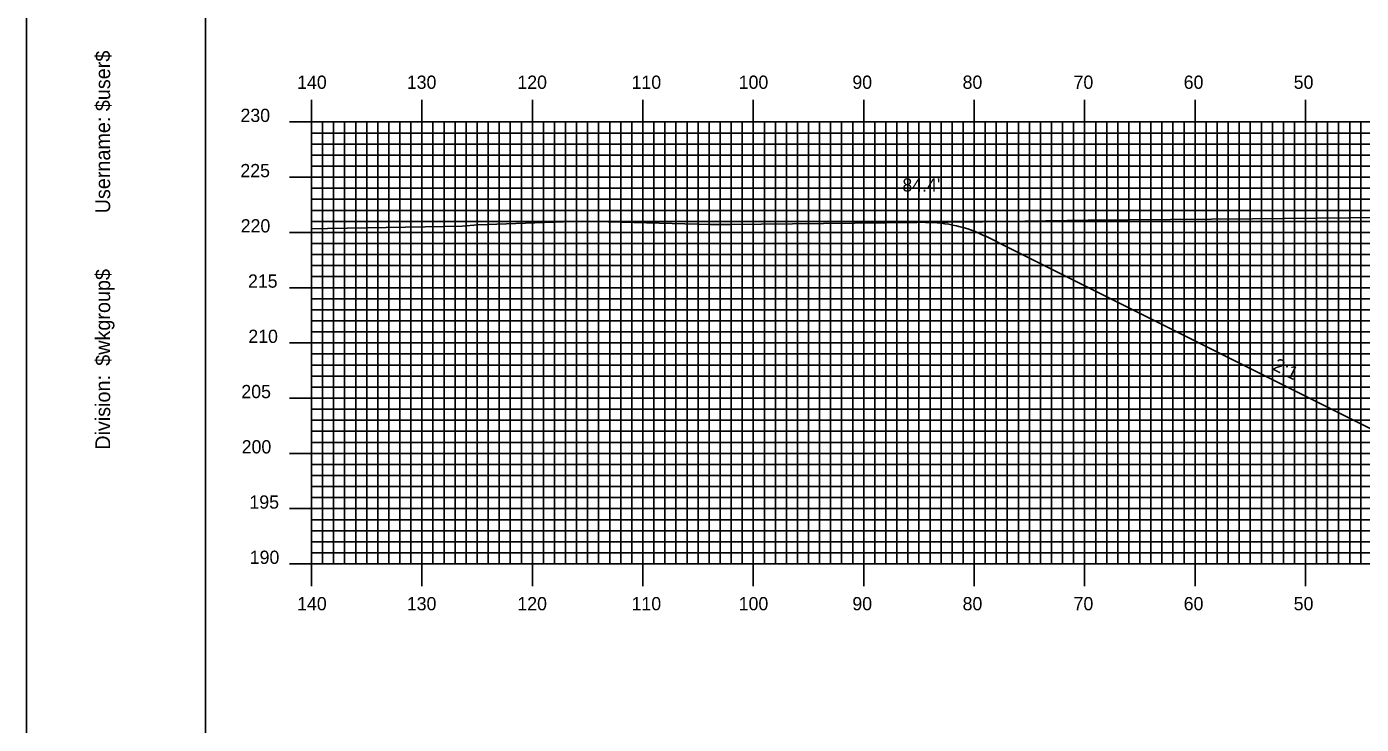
# Model space of a CAD drawing. Extents: x 1800749 to 1801092, y 442591 to 442811.
# Drawn here: x 1800748.8 to 1800869.6, y 442654.2 to 442717.3 of the extents above; entities that cross this region are included whole.
import ezdxf

# ---------------------------------------------------------------- set-up
doc = ezdxf.new("R2010")
doc.units = 0
for name, color, linetype in [('ANNOTATION', 7, 'Continuous'), ('BORDER', 7, 'Continuous'), ('D_Roadway_SlopeLines', 7, 'Continuous'), ('D_Text_Standard', 7, 'Continuous'), ('H_V ANNOTATION', 7, 'Continuous'), ('MAJOR', 7, 'Continuous'), ('MINOR', 7, 'Continuous'), ('PLOT BOUNDARY', 7, 'Continuous'), ('S_Roadway_Centerline', 7, 'Continuous')]:
    doc.layers.add(name, color=color, linetype=linetype)

msp = doc.modelspace()

# ---------------------------------------------------------------- linework, layer by layer
at = {"layer": 'ANNOTATION'}
msp.add_line((1800774.55, 442688.67), (1800774.55, 442689.27), dxfattribs=at)
msp.add_arc((1800830.24, 442687.58), 12, 63.4349, 90.4821, dxfattribs=at)
msp.add_arc((1800830.24, 442687.58), 12, 63.4349, 90.4821, dxfattribs=at)
at = {"layer": 'BORDER'}
msp.add_lwpolyline([(1800764.95, 442596.67), (1801084.95, 442596.67), (1801084.95, 442806.67), (1800764.95, 442806.67)], close=True, dxfattribs=at)
at = {"layer": 'D_Roadway_SlopeLines'}
for p in [(1800835.6, 442698.32), (1800880.38, 442675.93)]:
    msp.add_line(p, (1800837.81, 442697.21), dxfattribs=at)
at = {"layer": 'MAJOR'}
for p, q in [((1800774.55, 442710.67), (1800774.55, 442708.67)), ((1800784.55, 442710.67), (1800784.55, 442708.67)), ((1800794.55, 442710.67), (1800794.55, 442708.67)), ((1800804.55, 442710.67), (1800804.55, 442708.67)), ((1800814.55, 442710.67), (1800814.55, 442708.67)), ((1800824.55, 442710.67), (1800824.55, 442708.67)), ((1800834.55, 442710.67), (1800834.55, 442708.67)), ((1800844.55, 442710.67), (1800844.55, 442708.67)), ((1800854.55, 442710.67), (1800854.55, 442708.67)), ((1800864.55, 442710.67), (1800864.55, 442708.67)), ((1800772.55, 442708.67), (1800774.55, 442708.67)), ((1800774.55, 442708.67), (1801054.55, 442708.67)), ((1800774.55, 442668.67), (1800774.55, 442708.67)), ((1800774.55, 442668.67), (1800774.55, 442708.67)), ((1800774.55, 442708.67), (1801054.55, 442708.67)), ((1800784.55, 442668.67), (1800784.55, 442708.67)), ((1800794.55, 442668.67), (1800794.55, 442708.67)), ((1800804.55, 442668.67), (1800804.55, 442708.67)), ((1800814.55, 442668.67), (1800814.55, 442708.67)), ((1800824.55, 442668.67), (1800824.55, 442708.67)), ((1800834.55, 442668.67), (1800834.55, 442708.67)), ((1800844.55, 442668.67), (1800844.55, 442708.67)), ((1800854.55, 442668.67), (1800854.55, 442708.67)), ((1800864.55, 442668.67), (1800864.55, 442708.67)), ((1800772.55, 442703.67), (1800774.55, 442703.67)), ((1800774.55, 442703.67), (1801054.55, 442703.67)), ((1800772.55, 442698.67), (1800774.55, 442698.67)), ((1800774.55, 442698.67), (1801054.55, 442698.67)), ((1800772.55, 442693.67), (1800774.55, 442693.67)), ((1800774.55, 442693.67), (1801054.55, 442693.67)), ((1800772.55, 442688.67), (1800774.55, 442688.67)), ((1800774.55, 442688.67), (1801054.55, 442688.67)), ((1800772.55, 442683.67), (1800774.55, 442683.67)), ((1800774.55, 442683.67), (1801054.55, 442683.67)), ((1800772.55, 442678.67), (1800774.55, 442678.67)), ((1800774.55, 442678.67), (1801054.55, 442678.67)), ((1800772.55, 442673.67), (1800774.55, 442673.67)), ((1800774.55, 442673.67), (1801054.55, 442673.67)), ((1800772.55, 442668.67), (1800774.55, 442668.67)), ((1800774.55, 442668.67), (1801054.55, 442668.67)), ((1800774.55, 442668.67), (1801054.55, 442668.67)), ((1800774.55, 442666.66), (1800774.55, 442668.67)), ((1800784.55, 442666.66), (1800784.55, 442668.67)), ((1800794.55, 442666.66), (1800794.55, 442668.67)), ((1800804.55, 442666.66), (1800804.55, 442668.67)), ((1800814.55, 442666.66), (1800814.55, 442668.67)), ((1800824.55, 442666.66), (1800824.55, 442668.67)), ((1800834.55, 442666.66), (1800834.55, 442668.67)), ((1800844.55, 442666.66), (1800844.55, 442668.67)), ((1800854.55, 442666.66), (1800854.55, 442668.67)), ((1800864.55, 442666.66), (1800864.55, 442668.67))]:
    msp.add_line(p, q, dxfattribs=at)
at = {"layer": 'MINOR'}
for p, q in [((1800774.55, 442707.67), (1801054.55, 442707.67)), ((1800774.55, 442707.67), (1800776.55, 442707.67)), ((1800775.55, 442668.67), (1800775.55, 442708.67)), ((1800776.55, 442668.67), (1800776.55, 442708.67)), ((1800777.55, 442668.67), (1800777.55, 442708.67)), ((1800778.55, 442668.67), (1800778.55, 442708.67)), ((1800779.55, 442668.67), (1800779.55, 442708.67)), ((1800780.55, 442668.67), (1800780.55, 442708.67)), ((1800781.55, 442668.67), (1800781.55, 442708.67)), ((1800782.55, 442668.67), (1800782.55, 442708.67)), ((1800783.55, 442668.67), (1800783.55, 442708.67)), ((1800785.55, 442668.67), (1800785.55, 442708.67)), ((1800786.55, 442668.67), (1800786.55, 442708.67)), ((1800787.55, 442668.67), (1800787.55, 442708.67)), ((1800788.55, 442668.67), (1800788.55, 442708.67)), ((1800789.55, 442668.67), (1800789.55, 442708.67)), ((1800790.55, 442668.67), (1800790.55, 442708.67)), ((1800791.55, 442668.67), (1800791.55, 442708.67)), ((1800792.55, 442668.67), (1800792.55, 442708.67)), ((1800793.55, 442668.67), (1800793.55, 442708.67)), ((1800795.55, 442668.67), (1800795.55, 442708.67)), ((1800796.55, 442668.67), (1800796.55, 442708.67)), ((1800797.55, 442668.67), (1800797.55, 442708.67)), ((1800798.55, 442668.67), (1800798.55, 442708.67)), ((1800799.55, 442668.67), (1800799.55, 442708.67)), ((1800800.55, 442668.67), (1800800.55, 442708.67)), ((1800801.55, 442668.67), (1800801.55, 442708.67)), ((1800802.55, 442668.67), (1800802.55, 442708.67)), ((1800803.55, 442668.67), (1800803.55, 442708.67)), ((1800805.55, 442668.67), (1800805.55, 442708.67)), ((1800806.55, 442668.67), (1800806.55, 442708.67)), ((1800807.55, 442668.67), (1800807.55, 442708.67)), ((1800808.55, 442668.67), (1800808.55, 442708.67)), ((1800809.55, 442668.67), (1800809.55, 442708.67)), ((1800810.55, 442668.67), (1800810.55, 442708.67)), ((1800811.55, 442668.67), (1800811.55, 442708.67)), ((1800812.55, 442668.67), (1800812.55, 442708.67)), ((1800813.55, 442668.67), (1800813.55, 442708.67)), ((1800815.55, 442668.67), (1800815.55, 442708.67)), ((1800816.55, 442668.67), (1800816.55, 442708.67)), ((1800817.55, 442668.67), (1800817.55, 442708.67)), ((1800818.55, 442668.67), (1800818.55, 442708.67)), ((1800819.55, 442668.67), (1800819.55, 442708.67)), ((1800820.55, 442668.67), (1800820.55, 442708.67)), ((1800821.55, 442668.67), (1800821.55, 442708.67)), ((1800822.55, 442668.67), (1800822.55, 442708.67)), ((1800823.55, 442668.67), (1800823.55, 442708.67)), ((1800825.55, 442668.67), (1800825.55, 442708.67)), ((1800826.55, 442668.67), (1800826.55, 442708.67)), ((1800827.55, 442668.67), (1800827.55, 442708.67)), ((1800828.55, 442668.67), (1800828.55, 442708.67)), ((1800829.55, 442668.67), (1800829.55, 442708.67)), ((1800830.55, 442668.67), (1800830.55, 442708.67)), ((1800831.55, 442668.67), (1800831.55, 442708.67)), ((1800832.55, 442668.67), (1800832.55, 442708.67)), ((1800833.55, 442668.67), (1800833.55, 442708.67)), ((1800835.55, 442668.67), (1800835.55, 442708.67)), ((1800836.55, 442668.67), (1800836.55, 442708.67)), ((1800837.55, 442668.67), (1800837.55, 442708.67)), ((1800838.55, 442668.67), (1800838.55, 442708.67)), ((1800839.55, 442668.67), (1800839.55, 442708.67)), ((1800840.55, 442668.67), (1800840.55, 442708.67)), ((1800841.55, 442668.67), (1800841.55, 442708.67)), ((1800842.55, 442668.67), (1800842.55, 442708.67)), ((1800843.55, 442668.67), (1800843.55, 442708.67)), ((1800845.55, 442668.67), (1800845.55, 442708.67)), ((1800846.55, 442668.67), (1800846.55, 442708.67)), ((1800847.55, 442668.67), (1800847.55, 442708.67)), ((1800848.55, 442668.67), (1800848.55, 442708.67)), ((1800849.55, 442668.67), (1800849.55, 442708.67)), ((1800850.55, 442668.67), (1800850.55, 442708.67)), ((1800851.55, 442668.67), (1800851.55, 442708.67)), ((1800852.55, 442668.67), (1800852.55, 442708.67)), ((1800853.55, 442668.67), (1800853.55, 442708.67)), ((1800855.55, 442668.67), (1800855.55, 442708.67)), ((1800856.55, 442668.67), (1800856.55, 442708.67)), ((1800857.55, 442668.67), (1800857.55, 442708.67)), ((1800858.55, 442668.67), (1800858.55, 442708.67)), ((1800859.55, 442668.67), (1800859.55, 442708.67)), ((1800860.55, 442668.67), (1800860.55, 442708.67)), ((1800861.55, 442668.67), (1800861.55, 442708.67)), ((1800862.55, 442668.67), (1800862.55, 442708.67)), ((1800863.55, 442668.67), (1800863.55, 442708.67)), ((1800865.55, 442668.67), (1800865.55, 442708.67)), ((1800866.55, 442668.67), (1800866.55, 442708.67)), ((1800867.55, 442668.67), (1800867.55, 442708.67)), ((1800868.55, 442668.67), (1800868.55, 442708.67)), ((1800869.55, 442668.67), (1800869.55, 442708.67)), ((1800774.55, 442706.67), (1801054.55, 442706.67)), ((1800774.55, 442706.67), (1800776.55, 442706.67)), ((1800774.55, 442705.67), (1801054.55, 442705.67)), ((1800774.55, 442705.67), (1800776.55, 442705.67)), ((1800774.55, 442704.67), (1801054.55, 442704.67)), ((1800774.55, 442704.67), (1800776.55, 442704.67)), ((1800774.55, 442702.67), (1801054.55, 442702.67)), ((1800774.55, 442702.67), (1800776.55, 442702.67)), ((1800774.55, 442701.67), (1801054.55, 442701.67)), ((1800774.55, 442701.67), (1800776.55, 442701.67)), ((1800774.55, 442700.67), (1801054.55, 442700.67)), ((1800774.55, 442700.67), (1800776.55, 442700.67)), ((1800774.55, 442699.67), (1801054.55, 442699.67)), ((1800774.55, 442699.67), (1800776.55, 442699.67)), ((1800774.55, 442697.67), (1801054.55, 442697.67)), ((1800774.55, 442697.67), (1800776.55, 442697.67)), ((1800774.55, 442696.67), (1801054.55, 442696.67)), ((1800774.55, 442696.67), (1800776.55, 442696.67)), ((1800774.55, 442695.67), (1801054.55, 442695.67)), ((1800774.55, 442695.67), (1800776.55, 442695.67)), ((1800774.55, 442694.67), (1801054.55, 442694.67)), ((1800774.55, 442694.67), (1800776.55, 442694.67)), ((1800774.55, 442692.67), (1801054.55, 442692.67)), ((1800774.55, 442692.67), (1800776.55, 442692.67)), ((1800774.55, 442691.67), (1801054.55, 442691.67)), ((1800774.55, 442691.67), (1800776.55, 442691.67)), ((1800774.55, 442690.67), (1801054.55, 442690.67)), ((1800774.55, 442690.67), (1800776.55, 442690.67)), ((1800774.55, 442689.67), (1801054.55, 442689.67)), ((1800774.55, 442689.67), (1800776.55, 442689.67)), ((1800774.55, 442687.67), (1801054.55, 442687.67)), ((1800774.55, 442687.67), (1800776.55, 442687.67)), ((1800774.55, 442686.67), (1801054.55, 442686.67)), ((1800774.55, 442686.67), (1800776.55, 442686.67)), ((1800774.55, 442685.67), (1801054.55, 442685.67)), ((1800774.55, 442685.67), (1800776.55, 442685.67)), ((1800774.55, 442684.67), (1801054.55, 442684.67)), ((1800774.55, 442684.67), (1800776.55, 442684.67)), ((1800774.55, 442682.67), (1801054.55, 442682.67)), ((1800774.55, 442682.67), (1800776.55, 442682.67)), ((1800774.55, 442681.67), (1801054.55, 442681.67)), ((1800774.55, 442681.67), (1800776.55, 442681.67)), ((1800774.55, 442680.67), (1801054.55, 442680.67)), ((1800774.55, 442680.67), (1800776.55, 442680.67)), ((1800774.55, 442679.67), (1801054.55, 442679.67)), ((1800774.55, 442679.67), (1800776.55, 442679.67)), ((1800774.55, 442677.67), (1801054.55, 442677.67)), ((1800774.55, 442677.67), (1800776.55, 442677.67)), ((1800774.55, 442676.67), (1801054.55, 442676.67)), ((1800774.55, 442676.67), (1800776.55, 442676.67)), ((1800774.55, 442675.67), (1801054.55, 442675.67)), ((1800774.55, 442675.67), (1800776.55, 442675.67)), ((1800774.55, 442674.67), (1801054.55, 442674.67)), ((1800774.55, 442674.67), (1800776.55, 442674.67)), ((1800774.55, 442672.67), (1801054.55, 442672.67)), ((1800774.55, 442672.67), (1800776.55, 442672.67)), ((1800774.55, 442671.67), (1801054.55, 442671.67)), ((1800774.55, 442671.67), (1800776.55, 442671.67)), ((1800774.55, 442670.67), (1801054.55, 442670.67)), ((1800774.55, 442670.67), (1800776.55, 442670.67)), ((1800774.55, 442669.67), (1801054.55, 442669.67)), ((1800774.55, 442669.67), (1800776.55, 442669.67))]:
    msp.add_line(p, q, dxfattribs=at)
at = {"layer": 'PLOT BOUNDARY'}
msp.add_lwpolyline([(1800748.76, 442590.55), (1801088.76, 442590.55), (1801088.76, 442810.55), (1800748.76, 442810.55)], close=True, dxfattribs=at)
at = {"layer": 'S_Roadway_Centerline'}
msp.add_lwpolyline([(1800774.55, 442699), (1800776, 442699.04), (1800784.83, 442699.18), (1800788.18, 442699.25), (1800789.62, 442699.35), (1800799.09, 442699.68), (1800810.67, 442699.38), (1800810.93, 442699.38), (1800812.45, 442699.4), (1800832.15, 442699.6), (1800835.3, 442699.63), (1800844.87, 442699.78), (1800859.76, 442699.91), (1800868.46, 442699.98), (1800875.56, 442700.01)], dxfattribs=at)

# ---------------------------------------------------------------- texts
at = {"layer": 'ANNOTATION'}
msp.add_text('2:1', height=1.2, rotation=333.4349, dxfattribs=at).set_placement((1800861.5, 442686.28))
msp.add_text('2:1', height=1.2, rotation=333.4349, dxfattribs=at).set_placement((1800861.5, 442686.28))
at = {"layer": 'BORDER'}
for s, p in [('$user$', (1800756.32, 442709.65)), ('Username:', (1800756.32, 442700.4)), ('$wkgroup$', (1800756.32, 442686.6)), ('Division:', (1800756.32, 442679))]:
    msp.add_text(s, height=1.339, rotation=90, dxfattribs=at).set_placement(p)
at = {"layer": 'D_Text_Standard'}
msp.add_text("84.4'", height=1.2, dxfattribs=at).set_placement((1800828.05, 442702.37))
at = {"layer": 'H_V ANNOTATION'}
for s, p in [('140', (1800773.25, 442711.67)), ('130', (1800783.18, 442711.67)), ('120', (1800793.19, 442711.67)), ('110', (1800803.53, 442711.67)), ('100', (1800813.23, 442711.67)), ('90', (1800823.52, 442711.67)), ('80', (1800833.5, 442711.67)), ('70', (1800843.55, 442711.67)), ('60', (1800853.52, 442711.67)), ('50', (1800863.48, 442711.67)), ('230', (1800768.12, 442708.67)), ('225', (1800768.11, 442703.67)), ('220', (1800768.14, 442698.67)), ('215', (1800768.8, 442693.67)), ('210', (1800768.83, 442688.67)), ('205', (1800768.2, 442683.67)), ('200', (1800768.23, 442678.67)), ('195', (1800768.93, 442673.67)), ('190', (1800768.96, 442668.67)), ('140', (1800773.25, 442664.47)), ('130', (1800783.18, 442664.47)), ('120', (1800793.19, 442664.47)), ('110', (1800803.53, 442664.47)), ('100', (1800813.23, 442664.47)), ('90', (1800823.52, 442664.47)), ('80', (1800833.5, 442664.47)), ('70', (1800843.55, 442664.47)), ('60', (1800853.52, 442664.47)), ('50', (1800863.48, 442664.47))]:
    msp.add_text(s, height=1.2, dxfattribs=at).set_placement(p)
at = {"layer": 'MAJOR'}
msp.add_text('-', height=0.012, dxfattribs=at).set_placement((1800774.54, 442668.67))

doc.saveas('drawing.dxf')
